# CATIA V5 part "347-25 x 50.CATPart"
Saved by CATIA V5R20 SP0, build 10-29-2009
Part number: 347-25 x 50
Definition: NONE
Nomenclature: 347-25 x 50
Source: Unknown
Description: 347-25 x 50
Bounding box of the stored display mesh (mm): x 0 to 50, y -18 to 18, z -18 to 18
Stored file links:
  C:\Users\Utente\Desktop\IO LAVORO\3D X SITO CF\X SITO\3D files 347\347-25 x 50.CATPart
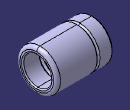
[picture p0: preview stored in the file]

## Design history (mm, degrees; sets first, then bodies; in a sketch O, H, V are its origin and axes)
Body1 "347-25 x 50" (main body)
  Solid1: solid without history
